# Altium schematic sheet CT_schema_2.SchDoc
size 522 x 390 mm
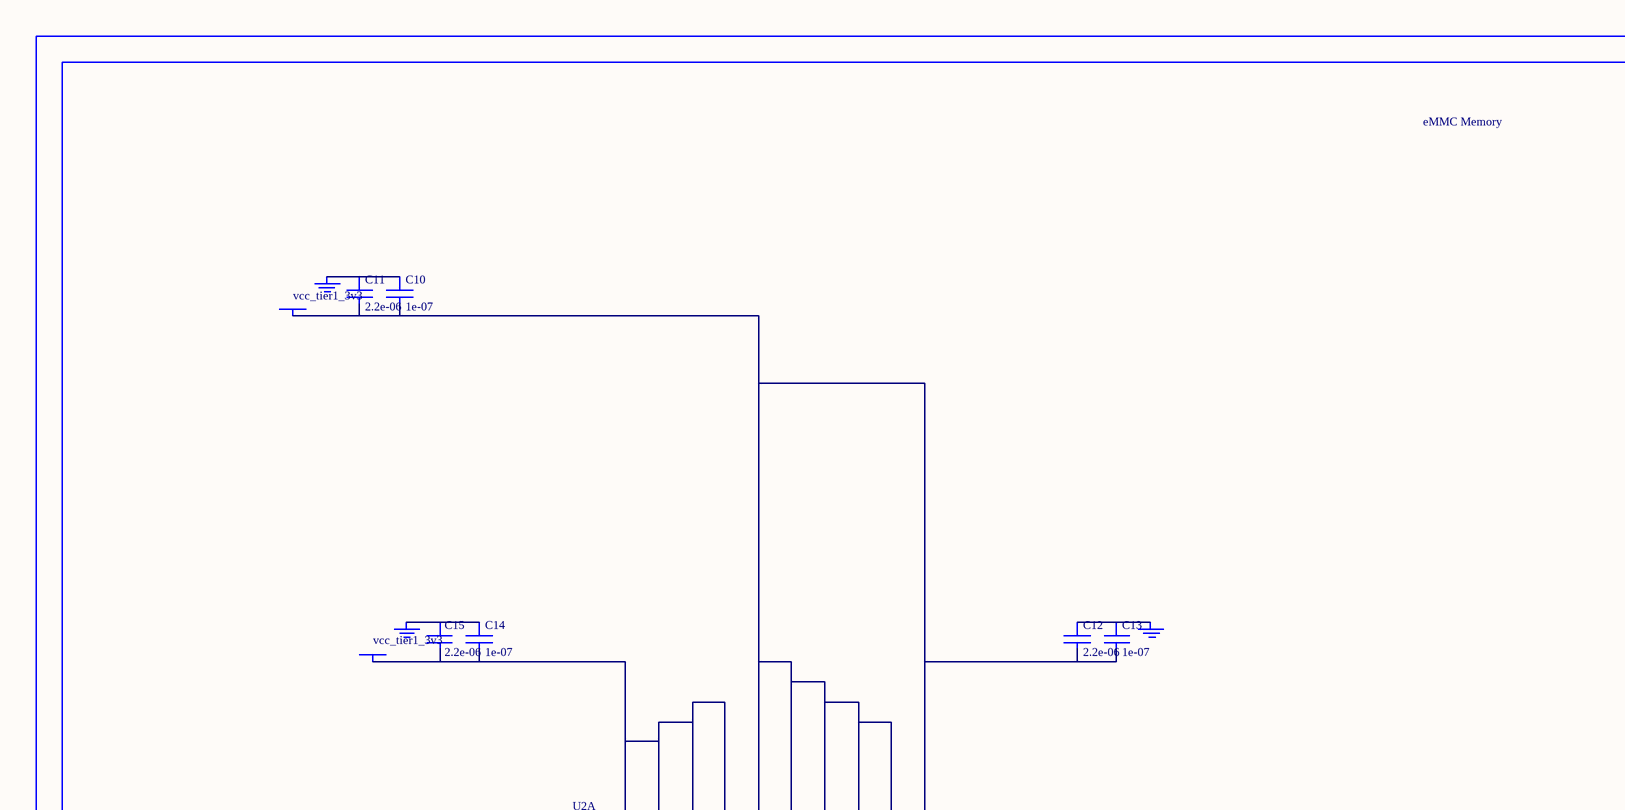
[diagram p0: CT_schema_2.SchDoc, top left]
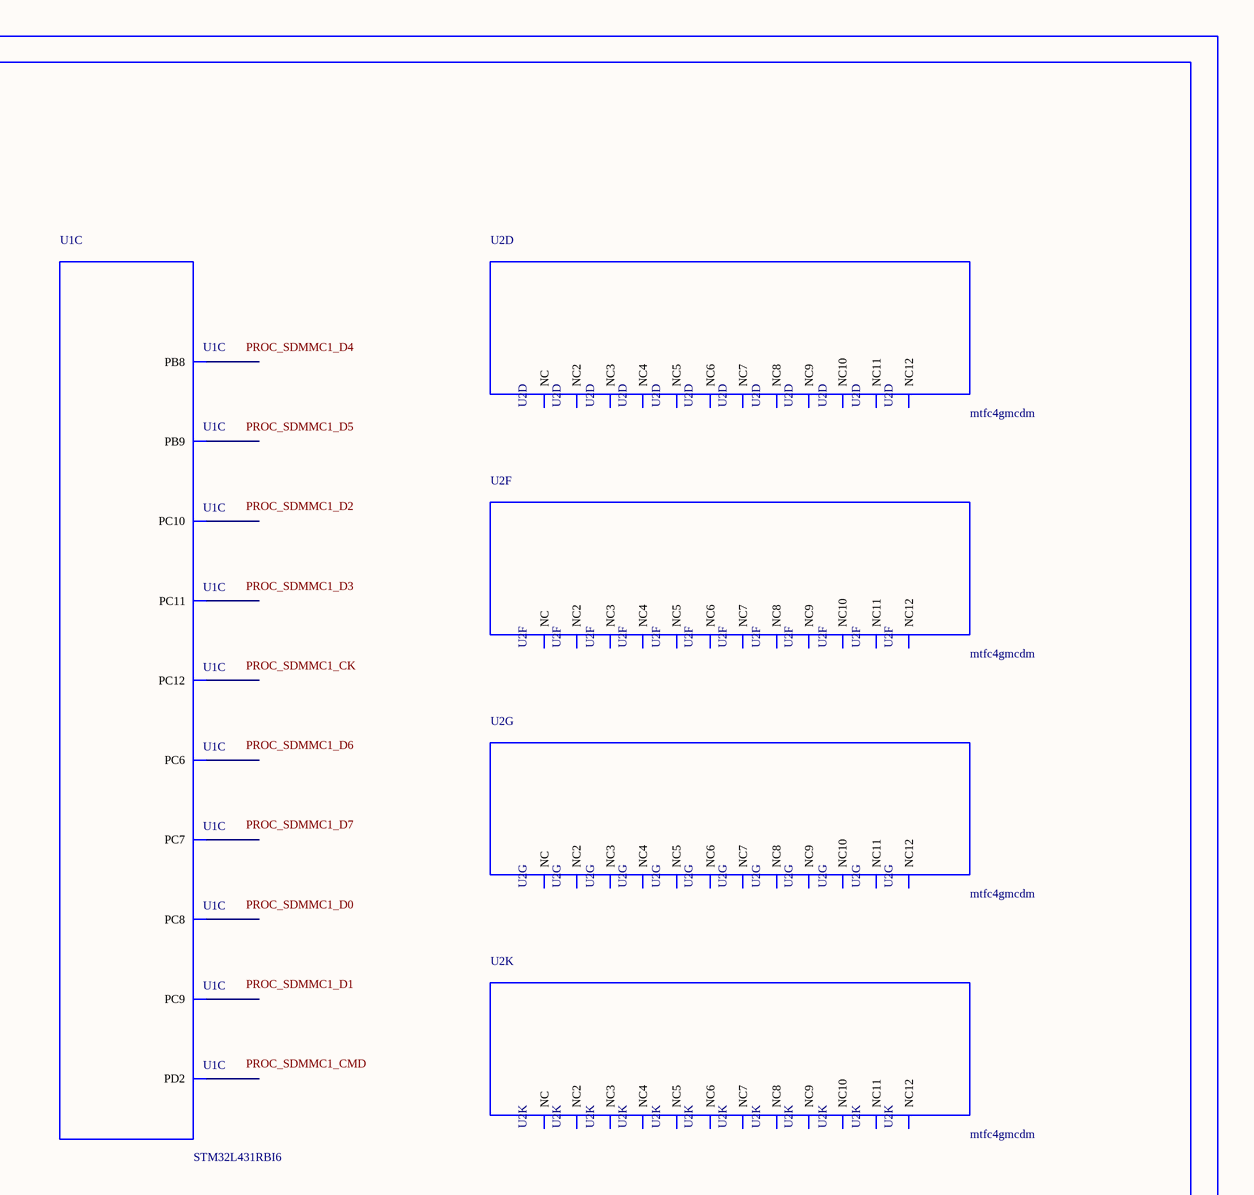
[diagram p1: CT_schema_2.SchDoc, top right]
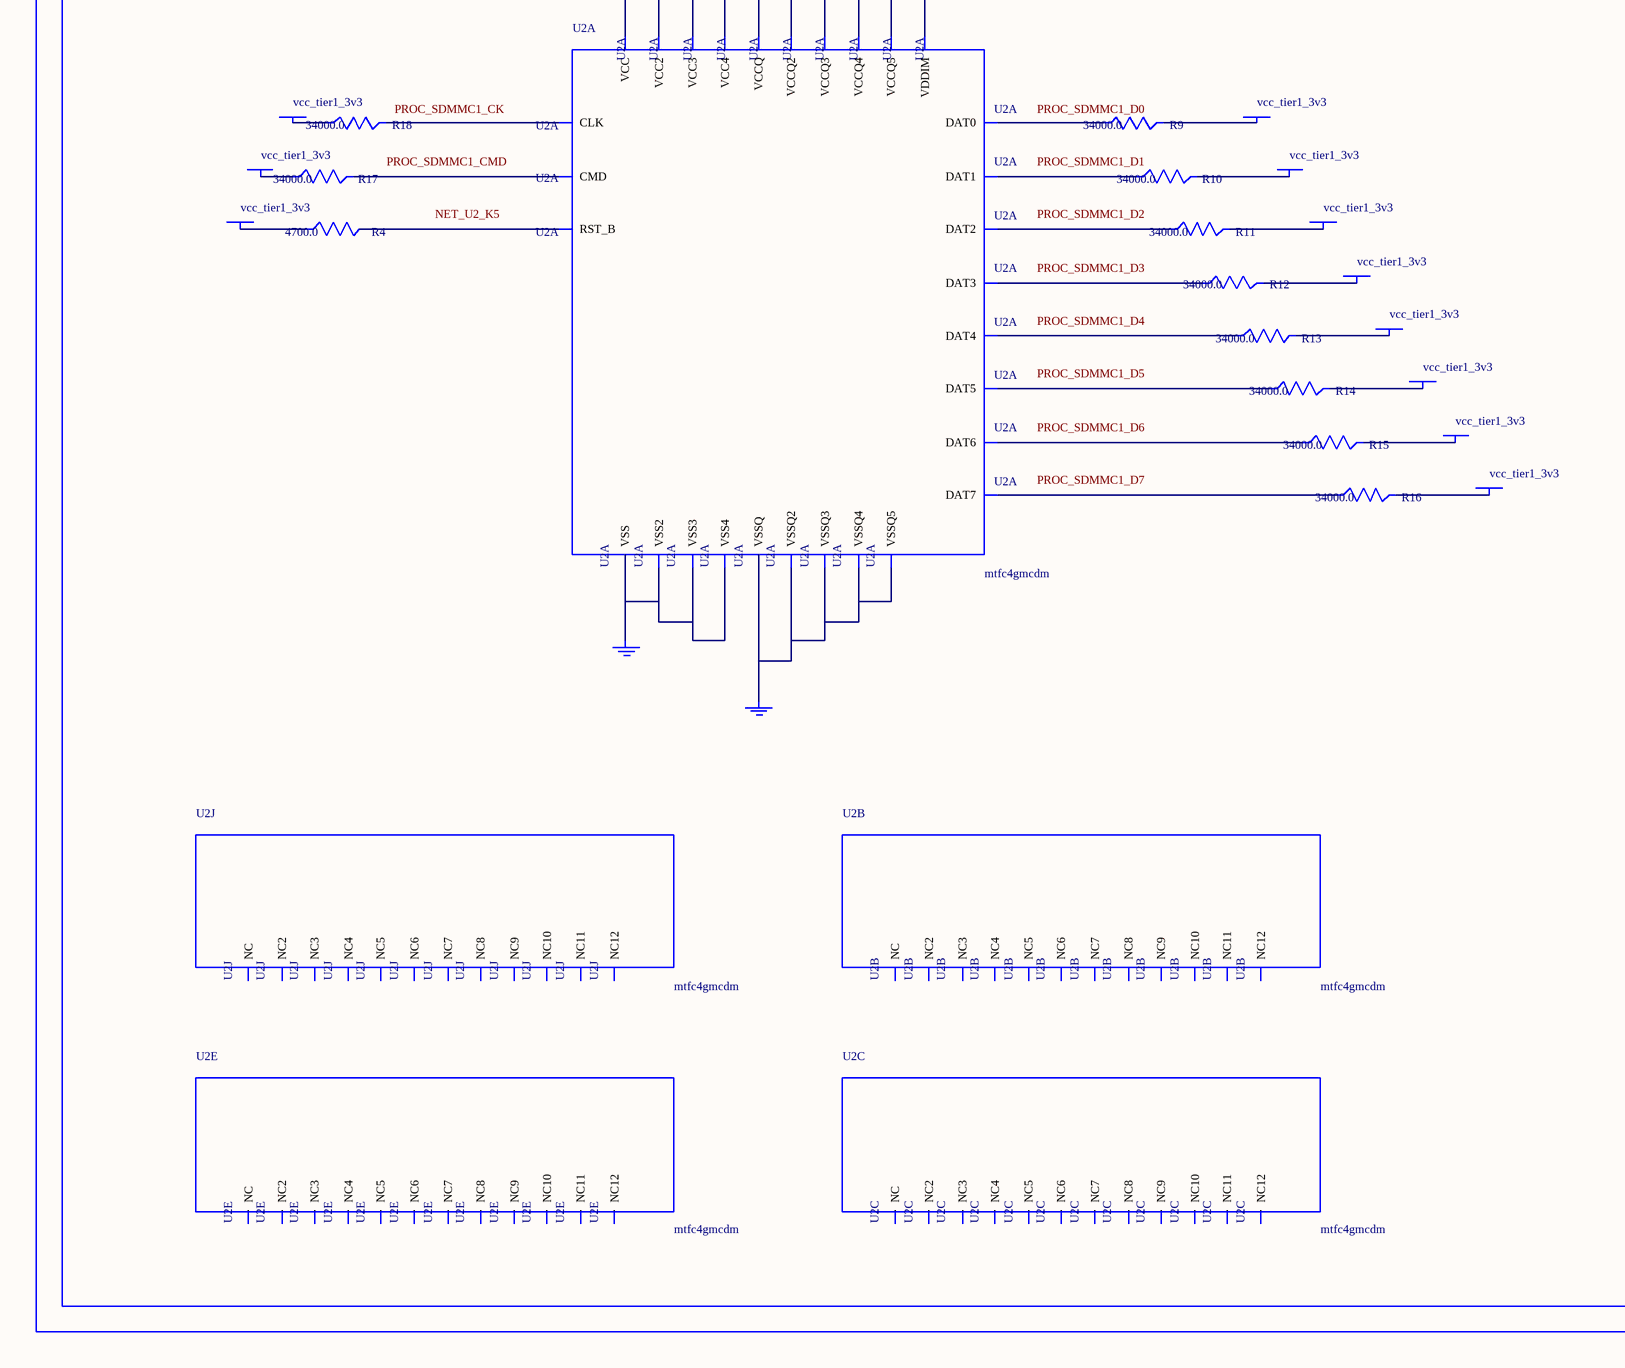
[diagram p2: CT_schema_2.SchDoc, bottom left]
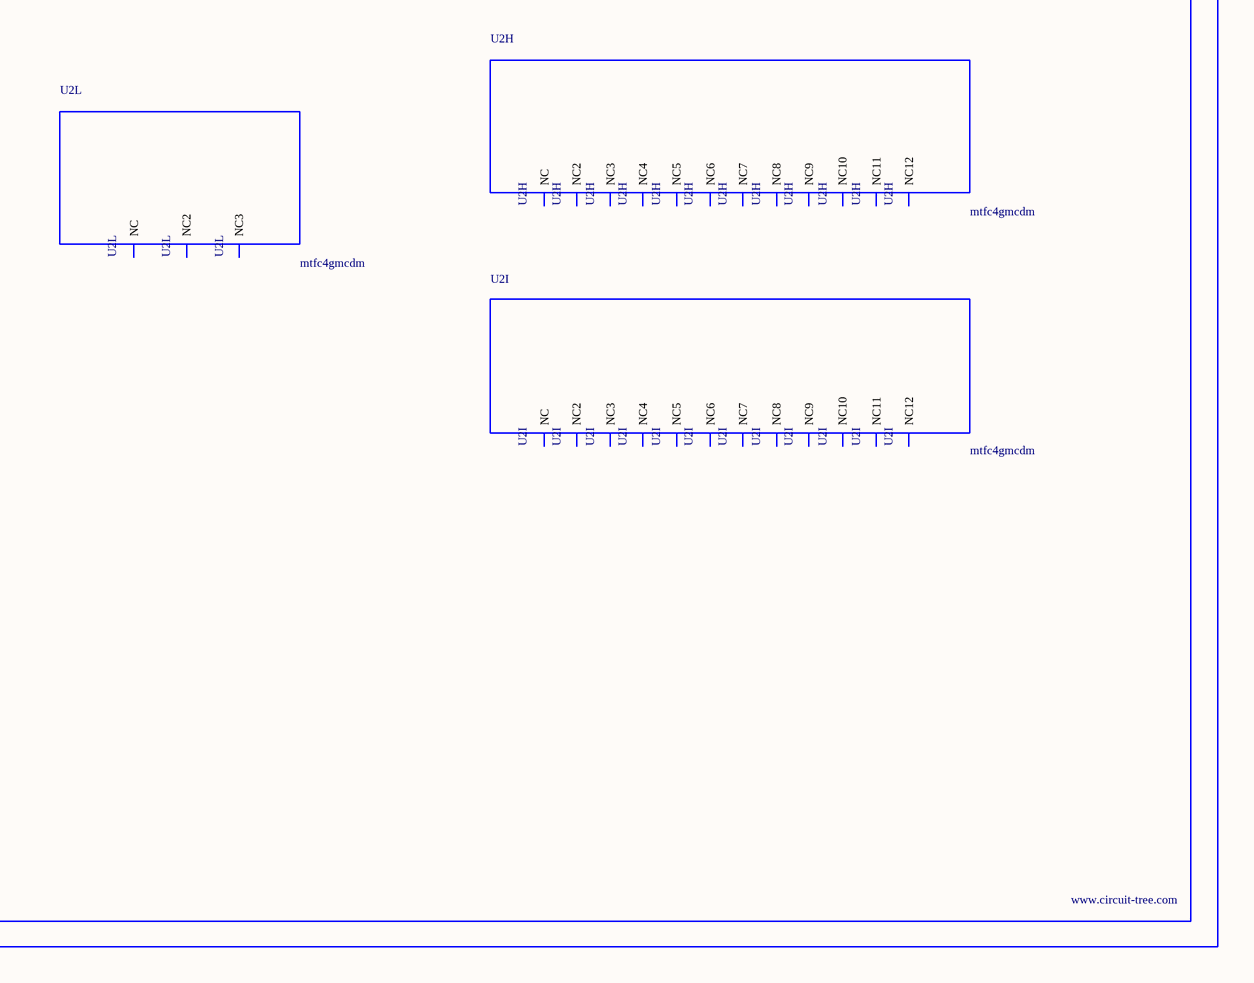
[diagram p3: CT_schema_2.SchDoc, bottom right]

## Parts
BORDER1  (no value)
C10  1e-07  [C0402]
C11  2.2e-06  [C0603]
C12  2.2e-06  [C0603]
C13  1e-07  [C0402]
C14  1e-07  [C0402]
C15  2.2e-06  [C0603]
GND_INSTANCE_1_0  (no value)
GND_INSTANCE_1_1  (no value)
GND_INSTANCE_1_2  (no value)
GND_INSTANCE_1_3  (no value)
GND_INSTANCE_1_4  (no value)
POWER_INSTANCE_1_0  vcc_tier1_3v3
POWER_INSTANCE_1_1  vcc_tier1_3v3
POWER_INSTANCE_1_2  vcc_tier1_3v3
POWER_INSTANCE_1_3  vcc_tier1_3v3
POWER_INSTANCE_1_4  vcc_tier1_3v3
POWER_INSTANCE_1_5  vcc_tier1_3v3
POWER_INSTANCE_1_6  vcc_tier1_3v3
POWER_INSTANCE_1_7  vcc_tier1_3v3
POWER_INSTANCE_1_8  vcc_tier1_3v3
POWER_INSTANCE_1_9  vcc_tier1_3v3
POWER_INSTANCE_1_10  vcc_tier1_3v3
POWER_INSTANCE_1_11  vcc_tier1_3v3
POWER_INSTANCE_1_12  vcc_tier1_3v3
R4  4700.0  [R0603]
R9  34000.0  [R0603]
R10  34000.0  [R0603]
R11  34000.0  [R0603]
R12  34000.0  [R0603]
R13  34000.0  [R0603]
R14  34000.0  [R0603]
R15  34000.0  [R0603]
R16  34000.0  [R0603]
R17  34000.0  [R0603]
R18  34000.0  [R0603]
U1  STM32L431RBI6  [UFBGA64]  (part C of 6)
U2  mtfc4gmcdm  [TFBGA-153]  (parts A,B,C,D,E,F,G,H,I,J,K,L of 12)

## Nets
NetC10_1: C10.1 C11.1 GND_INSTANCE_1_0.0(GND)
NetC10_2: C10.2 C11.2 C12.2 C13.2 POWER_INSTANCE_1_0.0(PWR) U2.C2(VDDIM) U2.C6(VCCQ) U2.M4(VCCQ2) U2.N4(VCCQ3) U2.P3(VCCQ4) U2.P5(VCCQ5)
NetC12_1: C12.1 C13.1 GND_INSTANCE_1_1.0(GND)
NetC14_1: C14.1 C15.1 GND_INSTANCE_1_2.0(GND)
NetC14_2: C14.2 C15.2 POWER_INSTANCE_1_1.0(PWR) U2.E6(VCC) U2.F5(VCC2) U2.J10(VCC3) U2.K9(VCC4)
NetGND_INSTANCE_1_3_0: GND_INSTANCE_1_3.0(GND) U2.E7(VSS) U2.G5(VSS2) U2.H10(VSS3) U2.K8(VSS4)
NetGND_INSTANCE_1_4_0: GND_INSTANCE_1_4.0(GND) U2.C4(VSSQ) U2.N2(VSSQ2) U2.N5(VSSQ3) U2.P4(VSSQ4) U2.P6(VSSQ5)
NetPOWER_INSTANCE_1_2_0: POWER_INSTANCE_1_2.0(PWR) R9.2
NetPOWER_INSTANCE_1_3_0: POWER_INSTANCE_1_3.0(PWR) R10.2
NetPOWER_INSTANCE_1_4_0: POWER_INSTANCE_1_4.0(PWR) R11.2
NetPOWER_INSTANCE_1_5_0: POWER_INSTANCE_1_5.0(PWR) R12.2
NetPOWER_INSTANCE_1_6_0: POWER_INSTANCE_1_6.0(PWR) R13.2
NetPOWER_INSTANCE_1_7_0: POWER_INSTANCE_1_7.0(PWR) R14.2
NetPOWER_INSTANCE_1_8_0: POWER_INSTANCE_1_8.0(PWR) R15.2
NetPOWER_INSTANCE_1_9_0: POWER_INSTANCE_1_9.0(PWR) R16.2
NetPOWER_INSTANCE_1_10_0: POWER_INSTANCE_1_10.0(PWR) R17.1
NetPOWER_INSTANCE_1_11_0: POWER_INSTANCE_1_11.0(PWR) R18.1
NetPOWER_INSTANCE_1_12_0: POWER_INSTANCE_1_12.0(PWR) R4.1
NetR4_2: R4.2 U2.K5(RST_B)
NetR9_1: R9.1 U2.A3(DAT0)
NetR10_1: R10.1 U2.A4(DAT1)
NetR11_1: R11.1 U2.A5(DAT2)
NetR12_1: R12.1 U2.B2(DAT3)
NetR13_1: R13.1 U2.B3(DAT4)
NetR14_1: R14.1 U2.B4(DAT5)
NetR15_1: R15.1 U2.B5(DAT6)
NetR16_1: R16.1 U2.B6(DAT7)
NetR17_2: R17.2 U2.M5(CMD)
NetR18_2: R18.2 U2.M6(CLK)

Not connected (* = marked no-connect by the designer): U1 A3(PB9) B3(PB8) B5(PD2) B6(PC11) B7(PC10) C5(PC12) D8(PC9) E7(PC7) E8(PC8) F6(PC6); U2 A1(NC) A2(NC7) A6(NC8) A7(NC9) A8(NC10) A9(NC11) A10(NC2) A11(NC3) A12(NC4) A13(NC5) A14(NC6) B1(NC12) B7(NC6) B8(NC7) B9(NC8) B10(NC) B11(NC2) B12(NC3) B13(NC4) B14(NC5) C1(NC9) C3(NC10) C5(NC11) C7(NC12) C8(NC6) C9(NC7) C10(NC) C11(NC2) C12(NC3) C13(NC4) C14(NC5) D1(NC8) D2(NC10) D3(NC11) D4(NC12) D12(NC9) D13(NC) D14(NC2) E1(NC3) E2(NC8) E3(NC9) E5(NC10) E8(NC11) E9(NC12) E10(NC4) E12(NC5) E13(NC6) E14(NC7) F1(NC) F2(NC6) F3(NC7) F10(NC2) F12(NC3) F13(NC4) F14(NC5) G1(NC8) G2(NC11) G3(NC12) G10(NC9) G12(NC10) G13(NC) G14(NC2) H1(NC3) H2(NC7) H3(NC8) H5(NC9) H12(NC4) H13(NC5) H14(NC6) J1(NC10) J2(NC11) J3(NC12) J5(NC4) J12(NC) J13(NC2) J14(NC3) K1(NC5) K2(NC9) K3(NC10) K6(NC11) K7(NC12) K10(NC6) K12(NC7) K13(NC8) K14(NC) L1(NC2) L2(NC6) L3(NC7) L12(NC3) L13(NC4) L14(NC5) M1(NC8) M2(NC9) M3(NC10) M7(NC11) M8(NC12) M9(NC6) M10(NC) M11(NC2) M12(NC3) M13(NC4) M14(NC5) N1(NC7) N3(NC8) N6(NC9) N7(NC10) N8(NC11) N9(NC12) N10(NC) N11(NC2) N12(NC3) N13(NC4) N14(NC5) P1(NC6) P2(NC9) P7(NC10) P8(NC11) P9(NC12) P10(NC7) P11(NC8) P12(NC) P13(NC2) P14(NC3)

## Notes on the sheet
- Labels drawn without touching a wire or pin: NET_U2_K5, PROC_SDMMC1_CK, PROC_SDMMC1_CMD, PROC_SDMMC1_D0, PROC_SDMMC1_D1, PROC_SDMMC1_D2, PROC_SDMMC1_D3, PROC_SDMMC1_D4, PROC_SDMMC1_D5, PROC_SDMMC1_D6, PROC_SDMMC1_D7

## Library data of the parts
BORDER1 = BORDER_PAGE1
C10 C13 C14 = C0402C104K3RACTU
C11 C12 C15 = C0603C225K8RACTU
GND_INSTANCE_1_0-GND_INSTANCE_1_4 = GND
POWER_INSTANCE_1_0-POWER_INSTANCE_1_12 = PWR
R4 = RC0603JR-074K7L
R9-R18 = ERA3ARB3402V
